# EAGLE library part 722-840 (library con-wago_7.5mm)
Serie 722, Federleiste mit abgewinkelten Einlötstiften / Series 722, Female connector with angled solder pins Polzahl / Pole No.: 10 Rastermaß / Pitch: 7.5 mm Bemessungsspannung / Rated Voltage: 630 V Nennstrom / Nominal Current: 12 A Lötstiftlänge: / Solder Pin Length: 5 mm Farbe / Color: lichtgrau / light gray Stand: 01.01.2012. Die jeweils aktuellen Daten zu diesem Artikel finden Sie in unserem Produktkatalog, den Sie unter www.wago.com einsehen können. As of: 01/01/2012. Please find the newest data for this article in our product catalogue, which can be viewed under www.wago.com.
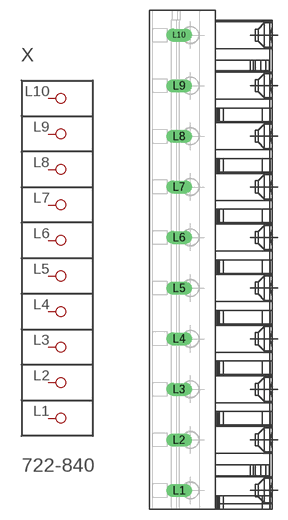
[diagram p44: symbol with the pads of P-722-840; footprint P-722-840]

Designator prefix X

## 722-840  [P-722-840]
L1  P1
L2  P2
L3  P3
L4  P4
L5  P5
L6  P6
L7  P7
L8  P8
L9  P9
L10  P10

## Footprint P-722-840 (pad centres in mm)
drill 1.3 long: L1 -5.114,-34.2; L2 -5.114,-26.7; L3 -5.114,-19.2; L4 -5.114,-11.7; L5 -5.114,-4.2; L6 -5.114,3.3; L7 -5.114,10.8; L8 -5.114,18.3; L9 -5.114,25.8; L10 -5.114,33.3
